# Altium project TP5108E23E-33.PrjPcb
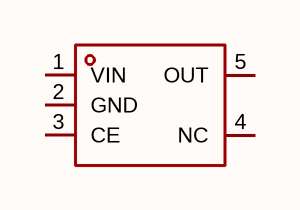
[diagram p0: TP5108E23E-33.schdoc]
1 sheet, 1 parts. Net scope: global (net labels, ports and power ports of the same name join across sheets).

## Sheet TP5108E23E-33.schdoc
size 127 x 101 mm

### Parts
U?  tp5108e23e-33  [SOT-23-5_L3.0-W1.7-P0.95-LS2.8-BL]  (value not drawn)

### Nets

Not connected (* = marked no-connect by the designer): U? 1(VIN) 2(GND) 3(CE) 4(NC) 5(OUT)

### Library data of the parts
U? = tp5108e23e-33: 输出极性:正极;工作电压:7V;输出电压:3.3V;输出电流:500mA;电源纹波抑制比(PSRR):70dB@(1kHz);输出类型:固定;; Manufacturer: TECH PUBLIC(台舟); AddInBom: yes; ModelId: 0a2a1b8f50944f73965918ad6e5fe167; ModelName: SOT-23-5_L2.9-W1.6-H1.1-LS2.8-P0.95; ModelTransform: 118.60433,114.173,0,90,0,0,0.0005,0.0005,0; Output Configuration: 正极; Voltage - Supply: 7V; Output Voltage: 3.3V; Output Current: 500mA; Voltage Dropout: 300mV@(200mA); standby current: 80uA; Noise: 50uVrms; Output Type: 固定; Number of Outputs: 1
